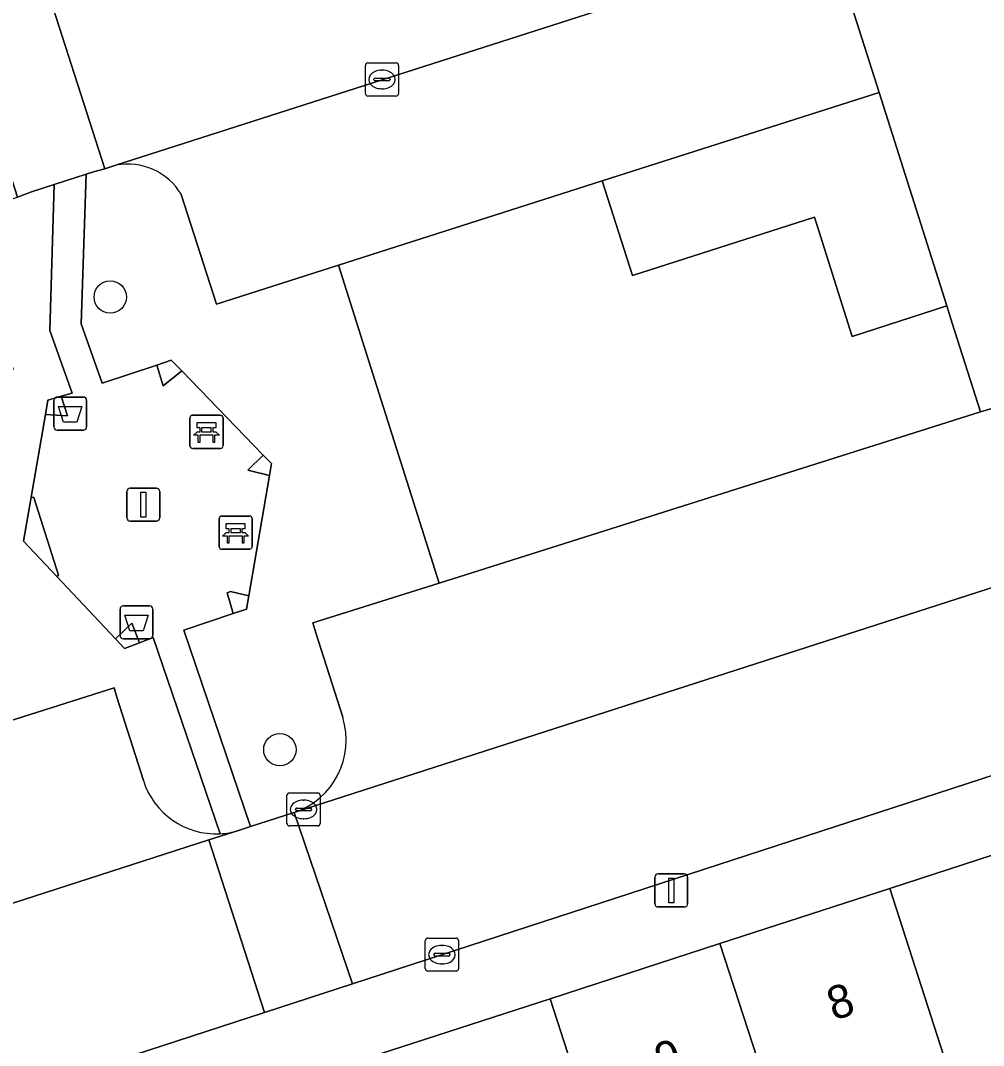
# Model space of a CAD drawing. Extents: x 159371 to 159986, y 382987 to 383597.
# Drawn here: x 159543.33 to 159572.4, y 383100.96 to 383131.92 of the extents above; entities that cross this region are included whole.
import ezdxf

# ---------------------------------------------------------------- set-up
doc = ezdxf.new("R2010")
doc.units = 0
for name, color, linetype in [('IMGEO_Afvalbak', 7, 'Continuous'), ('IMGEO_Bank', 7, 'Continuous'), ('IMGEO_Boom', 7, 'Continuous'), ('IMGEO_Groenvoorziening', 7, 'Continuous'), ('IMGEO_Kolk', 7, 'Continuous'), ('IMGEO_Lichtmast', 7, 'Continuous'), ('IMGEO_Pand', 7, 'Continuous'), ('IMGEO_Pand_nummerreeks', 7, 'Continuous'), ('IMGEO_Parkeervlak_open', 7, 'Continuous'), ('IMGEO_Rijbaan_lokaal_open', 7, 'Continuous'), ('IMGEO_Voetpad_halfverhard', 7, 'Continuous'), ('IMGEO_Voetpad_open', 7, 'Continuous')]:
    doc.layers.add(name, color=color, linetype=linetype)

msp = doc.modelspace()

# ---------------------------------------------------------------- linework, layer by layer
at = {"layer": 'IMGEO_Afvalbak'}
for p, q in [((159544.338, 383119.648), (159544.338, 383120.448)), ((159544.338, 383120.448), (159544.338, 383119.648)), ((159544.438, 383120.548), (159545.228, 383120.548)), ((159545.228, 383120.548), (159544.438, 383120.548)), ((159545.328, 383120.448), (159545.328, 383119.648)), ((159545.328, 383119.648), (159545.328, 383120.448)), ((159545.228, 383119.548), (159544.438, 383119.548)), ((159544.438, 383119.548), (159545.228, 383119.548)), ((159546.436, 383114.244), (159547.226, 383114.244)), ((159547.226, 383114.244), (159546.436, 383114.244)), ((159546.336, 383113.344), (159546.336, 383114.144)), ((159546.336, 383114.144), (159546.336, 383113.344)), ((159547.326, 383114.144), (159547.326, 383113.344)), ((159547.326, 383113.344), (159547.326, 383114.144)), ((159547.226, 383113.244), (159546.436, 383113.244)), ((159546.436, 383113.244), (159547.226, 383113.244))]:
    msp.add_line(p, q, dxfattribs=at)
for points in [[(159544.481, 383120.262), (159545.185, 383120.262), (159545.036, 383119.792), (159544.63, 383119.792), (159544.481, 383120.262)], [(159546.479, 383113.958), (159547.183, 383113.958), (159547.034, 383113.488), (159546.628, 383113.488), (159546.479, 383113.958)]]:
    msp.add_lwpolyline(points, dxfattribs=at)
for centre, start, end in [((159544.438, 383120.448), 90, 180), ((159544.438, 383120.448), 90, 180), ((159545.228, 383120.448), 0, 90), ((159545.228, 383120.448), 360, 90), ((159544.438, 383119.648), 180, 270), ((159544.438, 383119.648), 180, 270), ((159545.228, 383119.648), 270, 0), ((159545.228, 383119.648), 270, 0), ((159546.436, 383114.144), 90, 180), ((159546.436, 383114.144), 90, 180), ((159547.226, 383114.144), 0, 90), ((159547.226, 383114.144), 360, 90), ((159546.436, 383113.344), 180, 270), ((159546.436, 383113.344), 180, 270), ((159547.226, 383113.344), 270, 0), ((159547.226, 383113.344), 270, 0)]:
    msp.add_arc(centre, 0.1, start, end, dxfattribs=at)
at = {"layer": 'IMGEO_Bank'}
for p, q in [((159548.445, 383119.071), (159548.445, 383119.912)), ((159548.445, 383119.912), (159548.445, 383119.071)), ((159548.52, 383119.996), (159549.361, 383119.996)), ((159549.361, 383119.996), (159548.52, 383119.996)), ((159549.445, 383119.921), (159549.445, 383119.08)), ((159549.445, 383119.08), (159549.445, 383119.921)), ((159548.754, 383119.502), (159548.754, 383119.608)), ((159548.798, 383119.608), (159548.798, 383119.502)), ((159549.086, 383119.614), (159548.804, 383119.614)), ((159548.804, 383119.496), (159549.086, 383119.496)), ((159549.092, 383119.502), (159549.092, 383119.608)), ((159549.136, 383119.608), (159549.136, 383119.502)), ((159549.142, 383119.394), (159548.749, 383119.394)), ((159549.37, 383118.996), (159548.529, 383118.996)), ((159548.529, 383118.996), (159549.37, 383118.996)), ((159549.326, 383116.028), (159549.326, 383116.869)), ((159549.326, 383116.869), (159549.326, 383116.028)), ((159549.401, 383116.953), (159550.242, 383116.953)), ((159550.242, 383116.953), (159549.401, 383116.953)), ((159550.326, 383116.878), (159550.326, 383116.037)), ((159550.326, 383116.037), (159550.326, 383116.878)), ((159549.635, 383116.459), (159549.635, 383116.565)), ((159549.679, 383116.565), (159549.679, 383116.459)), ((159549.967, 383116.571), (159549.685, 383116.571)), ((159549.685, 383116.453), (159549.967, 383116.453)), ((159549.973, 383116.459), (159549.973, 383116.565)), ((159550.017, 383116.565), (159550.017, 383116.459)), ((159550.023, 383116.351), (159549.63, 383116.351)), ((159550.251, 383115.953), (159549.41, 383115.953)), ((159549.41, 383115.953), (159550.251, 383115.953))]:
    msp.add_line(p, q, dxfattribs=at)
for points in [[(159548.692, 383119.394), (159548.55, 383119.394), (159548.662, 383119.496), (159548.748, 383119.496)], [(159548.748, 383119.614), (159548.662, 383119.614), (159548.662, 383119.775), (159549.225, 383119.775), (159549.225, 383119.614), (159549.142, 383119.614)], [(159549.142, 383119.496), (159549.225, 383119.496), (159549.337, 383119.394), (159549.198, 383119.394)], [(159548.742, 383119.387), (159548.742, 383119.18), (159548.699, 383119.18), (159548.699, 383119.387)], [(159549.192, 383119.387), (159549.192, 383119.18), (159549.148, 383119.18), (159549.148, 383119.387)], [(159549.629, 383116.571), (159549.543, 383116.571), (159549.543, 383116.732), (159550.106, 383116.732), (159550.106, 383116.571), (159550.023, 383116.571)], [(159549.573, 383116.351), (159549.431, 383116.351), (159549.543, 383116.453), (159549.629, 383116.453)], [(159550.023, 383116.453), (159550.106, 383116.453), (159550.218, 383116.351), (159550.079, 383116.351)], [(159549.623, 383116.344), (159549.623, 383116.137), (159549.58, 383116.137), (159549.58, 383116.344)], [(159550.073, 383116.344), (159550.073, 383116.137), (159550.029, 383116.137), (159550.029, 383116.344)]]:
    msp.add_lwpolyline(points, dxfattribs=at)
for centre, radius, start, end in [((159548.523, 383119.918), 0.0779, 92.4484, 184.2845), ((159548.523, 383119.918), 0.0779, 92.4484, 184.2845), ((159549.367, 383119.918), 0.0779, 2.4484, 94.2845), ((159549.367, 383119.918), 0.0779, 2.4484, 94.2845), ((159548.747, 383119.607), 0.00671, 2.8957, 87.1043), ((159548.747, 383119.503), 0.00671, 272.8957, 357.1043), ((159548.804, 383119.607), 0.00671, 92.8957, 177.1043), ((159548.804, 383119.503), 0.00671, 182.8957, 267.1043), ((159549.086, 383119.607), 0.00671, 2.8957, 87.1043), ((159549.086, 383119.503), 0.00671, 272.8957, 357.1043), ((159549.143, 383119.607), 0.00671, 92.8957, 177.1043), ((159549.143, 383119.503), 0.00671, 182.8957, 267.1043), ((159548.692, 383119.387), 0.00671, 2.8957, 87.1043), ((159548.749, 383119.387), 0.00671, 92.8957, 177.1043), ((159549.141, 383119.387), 0.00671, 2.8957, 87.1043), ((159549.198, 383119.387), 0.00671, 92.8957, 177.1043), ((159548.523, 383119.074), 0.0779, 182.4484, 274.2845), ((159548.523, 383119.074), 0.0779, 182.4484, 274.2845), ((159549.367, 383119.074), 0.0779, 272.4484, 4.2845), ((159549.367, 383119.074), 0.0779, 272.4484, 4.2845), ((159549.404, 383116.875), 0.0779, 92.4484, 184.2845), ((159549.404, 383116.875), 0.0779, 92.4484, 184.2845), ((159550.248, 383116.875), 0.0779, 2.4484, 94.2845), ((159550.248, 383116.875), 0.0779, 2.4484, 94.2845), ((159549.628, 383116.564), 0.00671, 2.8957, 87.1043), ((159549.628, 383116.46), 0.00671, 272.8957, 357.1043), ((159549.685, 383116.564), 0.00671, 92.8957, 177.1043), ((159549.685, 383116.46), 0.00671, 182.8957, 267.1043), ((159549.967, 383116.564), 0.00671, 2.8957, 87.1043), ((159549.967, 383116.46), 0.00671, 272.8957, 357.1043), ((159550.024, 383116.564), 0.00671, 92.8957, 177.1043), ((159550.024, 383116.46), 0.00671, 182.8957, 267.1043), ((159549.573, 383116.344), 0.00671, 2.8957, 87.1043), ((159549.63, 383116.344), 0.00671, 92.8957, 177.1043), ((159550.022, 383116.344), 0.00671, 2.8957, 87.1043), ((159550.079, 383116.344), 0.00671, 92.8957, 177.1043), ((159549.404, 383116.031), 0.0779, 182.4484, 274.2845), ((159549.404, 383116.031), 0.0779, 182.4484, 274.2845), ((159550.248, 383116.031), 0.0779, 272.4484, 4.2845), ((159550.248, 383116.031), 0.0779, 272.4484, 4.2845)]:
    msp.add_arc(centre, radius, start, end, dxfattribs=at)
at = {"layer": 'IMGEO_Boom'}
for centre in [(159546.04, 383123.57), (159551.161, 383109.897)]:
    msp.add_circle(centre, 0.489, dxfattribs=at)
at = {"layer": 'IMGEO_Groenvoorziening'}
for points in [[(159568.059, 383133.514), (159569.251, 383129.752), (159571.294, 383123.299), (159571.459, 383122.778), (159572.307, 383120.099), (159572.649, 383120.207), (159573.679, 383116.948)], [(159546.211, 383127.551), (159545.88, 383127.445), (159545.538, 383127.352), (159545.314, 383127.28), (159545.161, 383122.758), (159545.794, 383120.965), (159547.442, 383121.513), (159547.884, 383121.66), (159548.198, 383121.336), (159550.658, 383118.797), (159550.906, 383118.542), (159550.844, 383118.175), (159550.226, 383114.542), (159550.158, 383114.146), (159549.753, 383114.009), (159548.266, 383113.506), (159550.271, 383107.573), (159551.592, 383107.999)], [(159544.217, 383122.557), (159544.352, 383126.971), (159543.66, 383126.749), (159543.244, 383126.59)], [(159552.25, 383113.426), (159552.156, 383113.724), (159555.969, 383114.93), (159553.836, 383121.665), (159552.93, 383124.528), (159549.248, 383123.349), (159548.186, 383126.668)], [(159542.278, 383124.005), (159543.109, 383121.384), (159539.299, 383120.164), (159542.373, 383110.568), (159546.154, 383111.766), (159546.242, 383111.488), (159547.042, 383108.961)], [(159549.354, 383107.358), (159547.332, 383113.284), (159546.924, 383113.129), (159546.472, 383112.957), (159546.197, 383113.249), (159544.43, 383115.124), (159543.419, 383116.198), (159543.65, 383117.526), (159544.083, 383120.022), (159544.158, 383120.452), (159544.563, 383120.57), (159544.892, 383120.666), (159544.217, 383122.557)], [(159553.057, 383110.875), (159552.25, 383113.426)]]:
    msp.add_lwpolyline(points, dxfattribs=at)
for points in [[(159569.251, 383129.752), (159560.89, 383127.076), (159561.803, 383124.221), (159567.297, 383125.984), (159568.44, 383122.376), (159571.294, 383123.299)], [(159567.297, 383125.984), (159561.803, 383124.221), (159560.89, 383127.076), (159552.93, 383124.528), (159553.836, 383121.665), (159555.969, 383114.93), (159572.307, 383120.099), (159571.459, 383122.778), (159571.294, 383123.299), (159568.44, 383122.376)], [(159548.198, 383121.336), (159547.884, 383121.66), (159547.442, 383121.513), (159547.633, 383120.882)], [(159544.083, 383120.022), (159544.745, 383119.98), (159544.563, 383120.57), (159544.158, 383120.452)], [(159550.844, 383118.175), (159550.906, 383118.542), (159550.658, 383118.797), (159550.196, 383118.336)], [(159544.43, 383115.124), (159544.479, 383115.166), (159543.736, 383117.513), (159543.65, 383117.526), (159543.419, 383116.198)], [(159549.753, 383114.009), (159550.158, 383114.146), (159550.226, 383114.542), (159549.669, 383114.673), (159549.569, 383114.637)], [(159546.924, 383113.129), (159546.69, 383113.715), (159546.197, 383113.249), (159546.472, 383112.957)]]:
    msp.add_lwpolyline(points, close=True, dxfattribs=at)
for centre, radius, start, end in [((159546.565, 383125.692), 1.893, 31.055, 100.7673), ((159550.862, 383110.182), 2.302, 288.4865, 17.526), ((159549.233, 383109.652), 2.297, 197.4994, 273.0305)]:
    msp.add_arc(centre, radius, start, end, dxfattribs=at)
at = {"layer": 'IMGEO_Kolk'}
for p, q in [((159553.818, 383130.64), (159554.67, 383130.64)), ((159553.743, 383129.714), (159553.743, 383130.566)), ((159554.231, 383130.42), (159554.256, 383130.42)), ((159554.744, 383130.566), (159554.744, 383129.714)), ((159554.002, 383130.134), (159554.002, 383130.146)), ((159554.44, 383130.097), (159554.042, 383130.097)), ((159554.045, 383130.183), (159554.443, 383130.183)), ((159554.486, 383130.146), (159554.486, 383130.134)), ((159554.254, 383129.86), (159554.229, 383129.86)), ((159554.67, 383129.64), (159553.818, 383129.64)), ((159551.376, 383107.666), (159551.376, 383108.518)), ((159551.451, 383108.592), (159552.303, 383108.592)), ((159551.864, 383108.372), (159551.889, 383108.372)), ((159552.377, 383108.518), (159552.377, 383107.666)), ((159551.635, 383108.086), (159551.635, 383108.098)), ((159552.073, 383108.049), (159551.675, 383108.049)), ((159551.678, 383108.135), (159552.076, 383108.135)), ((159552.119, 383108.098), (159552.119, 383108.086)), ((159551.887, 383107.812), (159551.862, 383107.812)), ((159552.303, 383107.592), (159551.451, 383107.592)), ((159555.552, 383103.28), (159555.552, 383104.132)), ((159555.627, 383104.206), (159556.479, 383104.206)), ((159556.553, 383104.132), (159556.553, 383103.28)), ((159555.811, 383103.7), (159555.811, 383103.712)), ((159555.854, 383103.749), (159556.252, 383103.749)), ((159556.04, 383103.986), (159556.065, 383103.986)), ((159556.295, 383103.712), (159556.295, 383103.7)), ((159556.249, 383103.663), (159555.851, 383103.663)), ((159556.063, 383103.426), (159556.038, 383103.426)), ((159556.479, 383103.206), (159555.627, 383103.206))]:
    msp.add_line(p, q, dxfattribs=at)
for points in [[(159553.818, 383130.64), (159554.67, 383130.64)], [(159553.743, 383129.714), (159553.743, 383130.566)], [(159554.744, 383130.566), (159554.744, 383129.714)], [(159554.67, 383129.64), (159553.818, 383129.64)], [(159551.376, 383107.666), (159551.376, 383108.518)], [(159551.451, 383108.592), (159552.303, 383108.592)], [(159552.377, 383108.518), (159552.377, 383107.666)], [(159552.303, 383107.592), (159551.451, 383107.592)], [(159555.552, 383103.28), (159555.552, 383104.132)], [(159555.627, 383104.206), (159556.479, 383104.206)], [(159556.553, 383104.132), (159556.553, 383103.28)], [(159556.479, 383103.206), (159555.627, 383103.206)]]:
    msp.add_lwpolyline(points, dxfattribs=at)
for centre, radius, start, end in [((159553.82, 383130.564), 0.0765, 91.552, 178.448), ((159553.82, 383130.564), 0.0765, 91.552, 178.448), ((159554.668, 383130.564), 0.0765, 1.552, 88.448), ((159554.668, 383130.564), 0.0765, 1.552, 88.448), ((159554.042, 383130.143), 0.0403, 85.8775, 175.7526), ((159554.039, 383130.133), 0.0366, 178.938, 274.7102), ((159554.443, 383130.14), 0.043, 264.8664, 352.4533), ((159554.447, 383130.145), 0.0386, 1.7309, 96.639), ((159553.82, 383129.716), 0.0765, 181.552, 268.448), ((159553.82, 383129.716), 0.0765, 181.552, 268.448), ((159554.668, 383129.716), 0.0765, 271.552, 358.448), ((159554.668, 383129.716), 0.0765, 271.552, 358.448), ((159551.453, 383108.516), 0.0765, 91.552, 178.448), ((159551.453, 383108.516), 0.0765, 91.552, 178.448), ((159552.301, 383108.516), 0.0765, 1.552, 88.448), ((159552.301, 383108.516), 0.0765, 1.552, 88.448), ((159551.675, 383108.095), 0.0403, 85.8775, 175.7526), ((159551.672, 383108.085), 0.0366, 178.938, 274.7102), ((159552.076, 383108.092), 0.043, 264.8664, 352.4533), ((159552.08, 383108.097), 0.0386, 1.7309, 96.639), ((159551.453, 383107.668), 0.0765, 181.552, 268.448), ((159551.453, 383107.668), 0.0765, 181.552, 268.448), ((159552.301, 383107.668), 0.0765, 271.552, 358.448), ((159552.301, 383107.668), 0.0765, 271.552, 358.448), ((159555.629, 383104.13), 0.0765, 91.552, 178.448), ((159555.629, 383104.13), 0.0765, 91.552, 178.448), ((159556.477, 383104.13), 0.0765, 1.552, 88.448), ((159556.477, 383104.13), 0.0765, 1.552, 88.448), ((159555.851, 383103.709), 0.0403, 85.8775, 175.7526), ((159555.848, 383103.699), 0.0366, 178.938, 274.7102), ((159556.252, 383103.706), 0.043, 264.8664, 352.4533), ((159556.256, 383103.711), 0.0386, 1.7309, 96.639), ((159555.629, 383103.282), 0.0765, 181.552, 268.448), ((159555.629, 383103.282), 0.0765, 181.552, 268.448), ((159556.477, 383103.282), 0.0765, 271.552, 358.448), ((159556.477, 383103.282), 0.0765, 271.552, 358.448)]:
    msp.add_arc(centre, radius, start, end, dxfattribs=at)
for centre, major_axis, ratio, start_param, end_param in [((159554.23, 383130.14), (-0.387, 0.002), 0.722429, 4.712389, 7.853982), ((159554.255, 383130.14), (-0.39, 0.002), 0.717154, 1.570796, 4.712389), ((159551.863, 383108.092), (-0.387, 0.002), 0.722429, 4.712389, 7.853982), ((159551.888, 383108.092), (-0.39, 0.002), 0.717154, 1.570796, 4.712389), ((159556.039, 383103.706), (-0.387, 0.002), 0.722429, 4.712389, 7.853982), ((159556.064, 383103.706), (-0.39, 0.002), 0.717154, 1.570796, 4.712389)]:
    msp.add_ellipse(centre, major_axis=major_axis, ratio=ratio, start_param=start_param, end_param=end_param, dxfattribs=at)
at = {"layer": 'IMGEO_Lichtmast'}
for p, q in [((159546.543, 383116.898), (159546.543, 383117.698)), ((159546.543, 383117.698), (159546.543, 383116.898)), ((159546.643, 383117.798), (159547.433, 383117.798)), ((159547.433, 383117.798), (159546.643, 383117.798)), ((159547.533, 383117.698), (159547.533, 383116.898)), ((159547.533, 383116.898), (159547.533, 383117.698)), ((159547.433, 383116.798), (159546.643, 383116.798)), ((159546.643, 383116.798), (159547.433, 383116.798)), ((159562.481, 383105.245), (159562.481, 383106.045)), ((159562.481, 383106.045), (159562.481, 383105.245)), ((159562.581, 383106.145), (159563.371, 383106.145)), ((159563.371, 383106.145), (159562.581, 383106.145)), ((159563.471, 383106.045), (159563.471, 383105.245)), ((159563.471, 383105.245), (159563.471, 383106.045)), ((159563.371, 383105.145), (159562.581, 383105.145)), ((159562.581, 383105.145), (159563.371, 383105.145))]:
    msp.add_line(p, q, dxfattribs=at)
for points in [[(159546.963, 383117.673), (159547.113, 383117.673), (159547.113, 383116.923), (159546.963, 383116.923), (159546.963, 383117.673)], [(159562.901, 383106.02), (159563.051, 383106.02), (159563.051, 383105.27), (159562.901, 383105.27), (159562.901, 383106.02)]]:
    msp.add_lwpolyline(points, dxfattribs=at)
for centre, start, end in [((159546.643, 383117.698), 90, 180), ((159546.643, 383117.698), 90, 180), ((159547.433, 383117.698), 0, 90), ((159547.433, 383117.698), 360, 90), ((159546.643, 383116.898), 180, 270), ((159546.643, 383116.898), 180, 270), ((159547.433, 383116.898), 270, 0), ((159547.433, 383116.898), 270, 0), ((159562.581, 383106.045), 90, 180), ((159562.581, 383106.045), 90, 180), ((159563.371, 383106.045), 0, 90), ((159563.371, 383106.045), 360, 90), ((159562.581, 383105.245), 180, 270), ((159562.581, 383105.245), 180, 270), ((159563.371, 383105.245), 270, 0), ((159563.371, 383105.245), 270, 0)]:
    msp.add_arc(centre, 0.1, start, end, dxfattribs=at)
at = {"layer": 'IMGEO_Pand'}
for points in [[(159569.577, 383105.707), (159572.256, 383097.384), (159572.778, 383097.554), (159577.533, 383099.097), (159576.724, 383101.831), (159575.821, 383104.635), (159574.918, 383107.441)], [(159569.577, 383105.707), (159564.446, 383104.041), (159567.152, 383095.728), (159572.256, 383097.384)], [(159559.316, 383102.376), (159562.01, 383094.058), (159567.152, 383095.728), (159564.446, 383104.041)], [(159559.316, 383102.376), (159554.184, 383100.71), (159556.888, 383092.396), (159562.01, 383094.058)]]:
    msp.add_lwpolyline(points, close=True, dxfattribs=at)
at = {"layer": 'IMGEO_Parkeervlak_open'}
for points in [[(159568.704, 383134.767), (159546.211, 383127.551)], [(159569.251, 383129.752), (159568.059, 383133.514)], [(159548.186, 383126.668), (159549.248, 383123.349), (159552.93, 383124.528), (159560.89, 383127.076), (159569.251, 383129.752)], [(159573.679, 383116.948), (159572.649, 383120.207), (159572.307, 383120.099), (159555.969, 383114.93), (159552.156, 383113.724), (159552.25, 383113.426), (159553.057, 383110.875)], [(159551.592, 383107.999), (159575.853, 383115.826)], [(159547.042, 383108.961), (159546.242, 383111.488), (159546.154, 383111.766), (159542.373, 383110.568), (159542.341, 383110.558), (159539.767, 383109.743), (159539.766, 383109.743), (159530.436, 383106.788), (159531.568, 383103.212)], [(159549.018, 383107.169), (159549.915, 383107.458)], [(159530.567, 383101.218), (159549.018, 383107.169)]]:
    msp.add_lwpolyline(points, dxfattribs=at)
for centre, radius, start, end in [((159546.565, 383125.692), 1.893, 31.055, 100.7673), ((159550.862, 383110.182), 2.302, 288.4865, 17.526), ((159549.233, 383109.652), 2.297, 197.4994, 273.0305), ((159549.248, 383109.578), 2.223, 272.7431, 287.4709)]:
    msp.add_arc(centre, radius, start, end, dxfattribs=at)
at = {"layer": 'IMGEO_Rijbaan_lokaal_open'}
for points in [[(159554.613, 383136.241), (159544.136, 383132.87), (159545.88, 383127.445), (159546.211, 383127.551), (159568.704, 383134.767), (159572.156, 383135.872)], [(159523.837, 383120.403), (159543.244, 383126.59), (159541.49, 383132.018), (159516.455, 383123.963), (159516.506, 383123.807), (159512.682, 383122.594), (159512.597, 383122.856), (159512.311, 383122.762), (159522.735, 383090.553), (159526.812, 383091.837), (159526.127, 383093.955), (159550.697, 383101.96), (159549.018, 383107.169), (159530.567, 383101.218)], [(159578.043, 383116.532), (159576.075, 383115.897), (159575.96, 383115.86), (159575.853, 383115.826), (159551.592, 383107.999), (159553.35, 383102.825), (159578.967, 383111.171)]]:
    msp.add_lwpolyline(points, dxfattribs=at)
for points in [[(159545.314, 383127.28), (159545.538, 383127.352), (159545.88, 383127.445), (159544.136, 383132.87), (159541.49, 383132.018), (159543.244, 383126.59), (159543.66, 383126.749), (159544.352, 383126.971)], [(159550.271, 383107.573), (159549.915, 383107.458), (159549.018, 383107.169), (159550.697, 383101.96), (159553.35, 383102.825), (159551.592, 383107.999)]]:
    msp.add_lwpolyline(points, close=True, dxfattribs=at)
at = {"layer": 'IMGEO_Voetpad_halfverhard'}
msp.add_lwpolyline([(159549.915, 383107.458), (159550.271, 383107.573), (159548.266, 383113.506), (159549.753, 383114.009), (159549.569, 383114.637), (159549.669, 383114.673), (159550.226, 383114.542), (159550.844, 383118.175), (159550.196, 383118.336), (159550.658, 383118.797), (159548.198, 383121.336), (159547.633, 383120.882), (159547.442, 383121.513), (159545.794, 383120.965), (159545.161, 383122.758), (159545.314, 383127.28), (159544.352, 383126.971), (159544.217, 383122.557), (159544.892, 383120.666), (159544.563, 383120.57), (159544.745, 383119.98), (159544.083, 383120.022), (159543.65, 383117.526), (159543.736, 383117.513), (159544.479, 383115.166), (159544.43, 383115.124), (159546.197, 383113.249), (159546.69, 383113.715), (159546.924, 383113.129), (159547.332, 383113.284), (159549.354, 383107.358)], dxfattribs=at)
msp.add_arc((159549.248, 383109.578), 2.223, 272.7431, 287.4709, dxfattribs=at)
at = {"layer": 'IMGEO_Voetpad_open'}
msp.add_lwpolyline([(159578.967, 383111.171), (159553.35, 383102.825), (159550.697, 383101.96), (159526.127, 383093.955), (159526.812, 383091.837), (159528.151, 383092.259), (159533.546, 383094.01), (159538.679, 383095.677), (159543.819, 383097.345), (159549.045, 383099.042), (159554.184, 383100.71), (159559.316, 383102.376), (159564.446, 383104.041), (159569.577, 383105.707), (159574.918, 383107.441), (159580.39, 383109.217), (159581.3, 383106.414), (159582.21, 383103.611), (159583.382, 383103.973), (159581.43, 383110.08)], dxfattribs=at)

# ---------------------------------------------------------------- texts
at = {"layer": 'IMGEO_Pand_nummerreeks'}
for s, p in [('8', (159567.878, 383101.706)), ('9', (159562.678, 383100.018))]:
    msp.add_text(s, height=1, rotation=17.985, dxfattribs=at).set_placement(p)

doc.saveas('drawing.dxf')
